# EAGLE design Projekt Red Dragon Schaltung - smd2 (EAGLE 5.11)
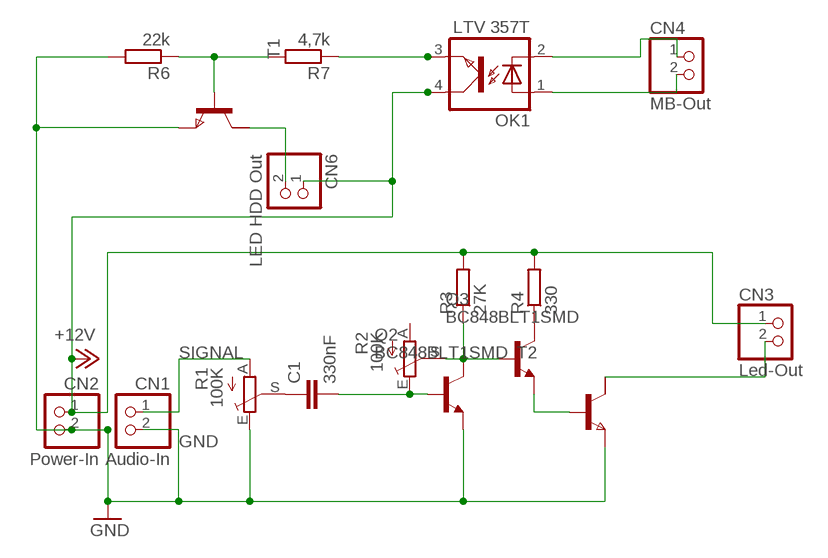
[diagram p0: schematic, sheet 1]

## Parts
C1  330nF  C-EU050-024X044  [C050-024X044]
CN1  Audio-In  PINHD-1X2  [1X02]
CN2  Power-In  PINHD-1X2  [1X02]
CN3  Led-Out  PINHD-1X2  [1X02]
CN4  MB-Out  PINHD-1X2  [1X02]
CN6  LED HDD Out  PINHD-1X2  [1X02]
OK1  LTV 357T  LTV816S  [SMD4]
Q2  BC848BLT1SMD  [SOT23]
Q3  BC848BLT1SMD  [SOT23]
R1  100K  TRIM_EU-S64W  [S64W]
R2  100K  TRIM_EU-S64W  [S64W]
R3  27K  R-EU_R1206  [R1206]
R4  330  R-EU_R1206  [R1206]
R6  22k  R-EU_R1206  [R1206]
R7  4,7k  R-EU_R1206  [R1206]
T1  NPNSOT223  [SOT223]
T2  NPNSOT223  [SOT223]

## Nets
+12V: CN2.1 CN3.1 CN6.1 OK1.4(COL) R3.2 R4.2
GND: CN1.2 CN2.2 Q2.2(E) R1.E R6.2 T1.3(E) T2.3(E)
N$1: C1.1 R1.S
N$2: C1.2 Q2.1(B) R2.E
N$3: Q2.3(C) Q3.1(B) R2.S R3.1
N$4: Q3.3(C) R4.1
N$5: Q3.2(E) T2.1(B)
N$6: CN4.1 OK1.2(C)
N$7: R6.1 R7.2 T1.1(B)
N$8: CN4.2 OK1.1(A)
N$9: CN3.2 T2.2(C1)
N$10: OK1.3(EMIT) R7.1
N$13: CN6.2 T1.2(C1)
SIGNAL: CN1.1 R1.A
Unconnected: R2.A T1.4(C2) T2.4(C2)

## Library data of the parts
C1 = rcl:C-EU: CAPACITOR, European symbol
CN1-CN4 CN6 = pinhead:PINHD-1X2: PIN HEADER
OK1 = optocoupler:LTV816: OPTO COUPLER Source: LITEON, LTV816.pdf
Q2 Q3 = transistor-npn:BC848*: NPN Transistor
R1 R2 = pot:TRIM_EU-: POTENTIOMETER
R3 R4 R6 R7 = rcl:R-EU_: RESISTOR, European symbol
T1 T2 = zetex:NPNSOT223: NPN TRANSISTOR; MPN: DJT4031N-13; OC_FARNELL: 1710672; OC_NEWARK: 25R4490

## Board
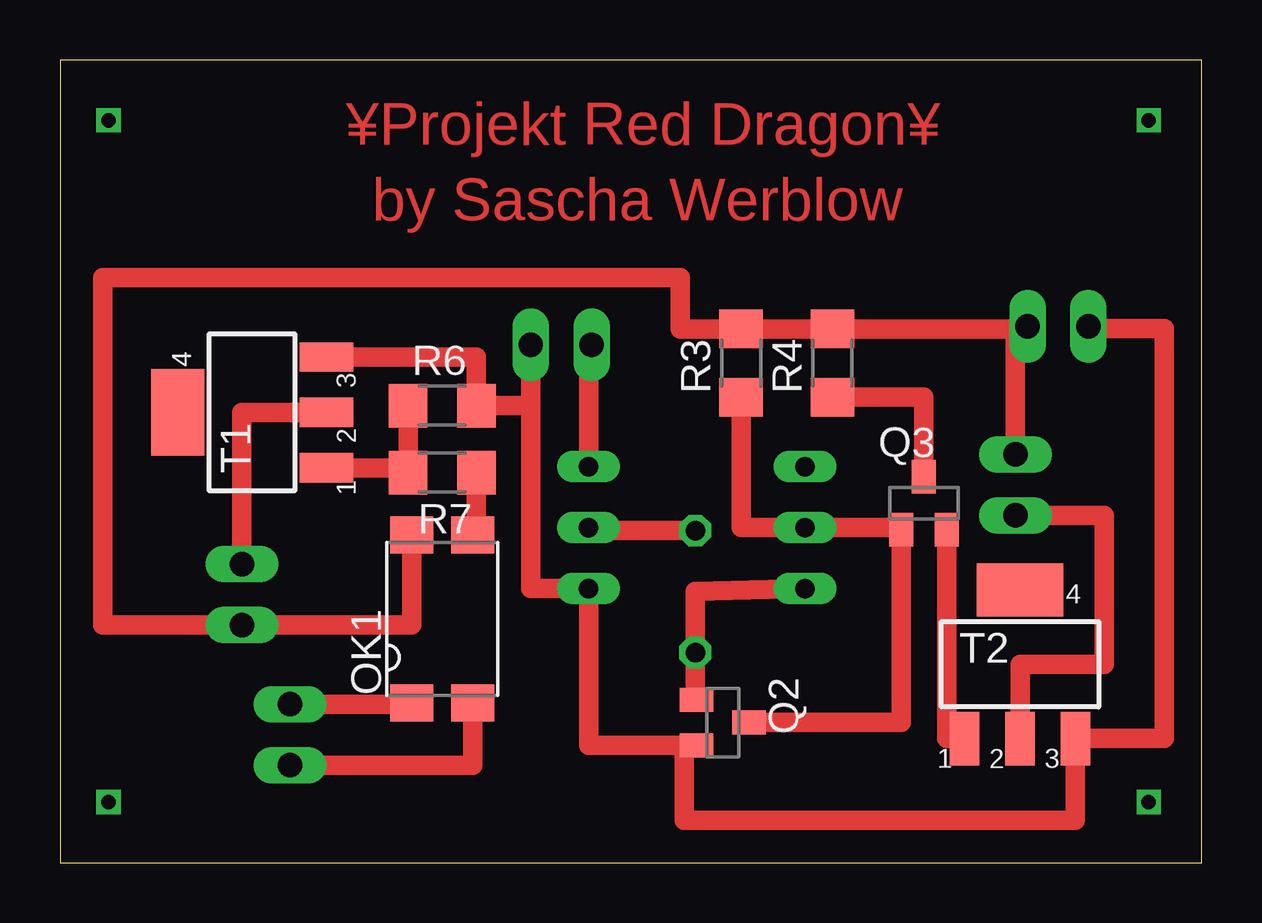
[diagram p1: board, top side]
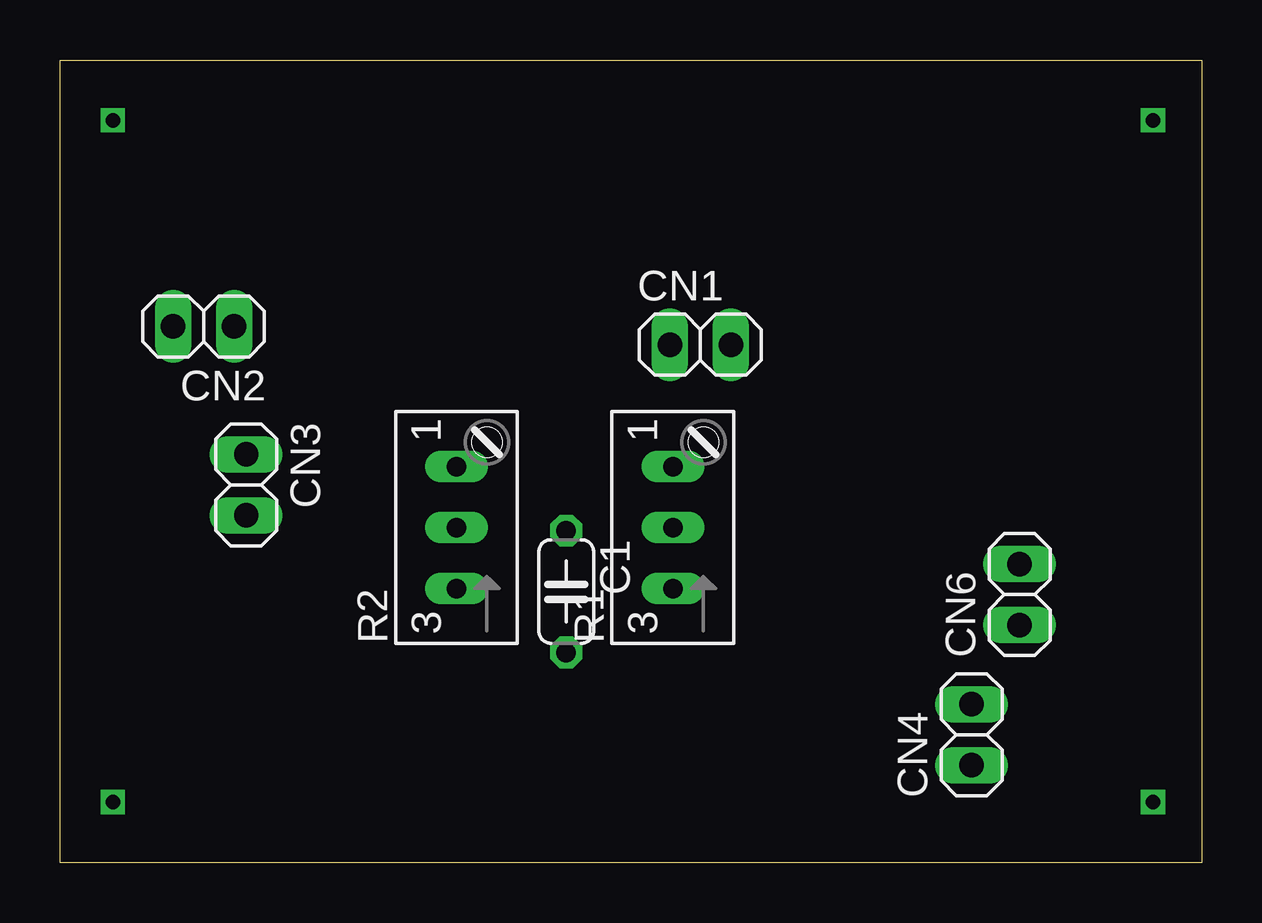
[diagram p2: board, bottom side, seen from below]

Size 47.56 x 33.46 mm. Coordinates in mm from the lower left corner, seen from the top.
Outline: 0,0 47.56,0 47.56,33.46 0,33.46 0,0
Copper layers (1*16): Top 0.035mm / dielectric 1.5mm / Bottom 0.035mm
Design rules "default": minimum track width 10mil, minimum drill 24mil, track to track 8mil, track to pad 8mil, pad to pad 8mil, via to via 8mil, smd to smd 8mil, copper to edge 40mil, drill to drill 8mil, minimum pad ring 10mil, minimum via ring 8mil, stop-mask expansion 4mil, vias tented up to drill 0mil, thermal gap 10mil

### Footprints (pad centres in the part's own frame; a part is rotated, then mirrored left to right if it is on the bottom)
C050-024X044 = drill 0.813 octagon: 1 -2.54,0; 2 2.54,0
1X02 = drill 1.016 long: 1 -1.27,0; 2 1.27,0
SMD4 = smd 1.78 x 1.55: 1 -1.27,-3.5; 2 1.27,-3.5; 3 1.27,3.5; 4 -1.27,3.5
SOT23 = smd 1 x 1.4: 1 -0.95,-1.1; 2 0.95,-1.1; 3 0,1.1
S64W = drill 0.813 long: A 2.54,1.27; E -2.54,1.27; S 0,1.27
R1206 = smd 1.6 x 1.803: 1 -1.422,0; 2 1.422,0
SOT223 = smd 1.219 x 2.235: 1 -2.311,-3.099; 2 0,-3.099; 3 2.311,-3.099 | smd 3.6 x 2.2: 4 0,3.099

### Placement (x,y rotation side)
C1  26.47,11.3 270 bottom
CN1  20.88,21.59 0 bottom
CN2  41.58,22.35 180 bottom
CN3  39.81,15.75 270 bottom
CN4  9.58,5.33 90 bottom
CN6  7.58,11.18 90 bottom
OK1  15.93,10.16 0 top
Q2  27.61,5.84 270 top
Q3  36,14.99 0 top
R1  20.76,13.97 90 bottom
R2  29.77,13.97 90 bottom
R3  28.38,20.83 90 top
R4  32.19,20.83 90 top
R6  15.93,19.05 0 top
R7  15.93,16.26 180 top
T1  8,18.77 90 top
T2  40,8.27 0 top

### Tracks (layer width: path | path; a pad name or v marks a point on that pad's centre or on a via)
+12V
  Top 0.813: OK1.4 14.66,9.91 CN6.1 1.78,9.91 1.78,24.38 25.84,24.38 25.84,22.25 R3.2 R4.2 39.81,22.25 | 39.81,22.25 CN3.1 | CN2.1 39.81,22.35 39.81,22.25
GND
  Top 0.813: 19.61,19.05 CN1.2 | 19.61,19.05 R6.2 17.35,21.08 T1.3 | 19.61,19.05 19.61,11.43 R1.E 22.03,4.89 Q2.2 26,4.89 26,1.77 42.31,1.77 T2.3 46,5.17 46,22.27 42.85,22.27 CN2.2
N$1
  Top 0.813: R1.S 22.03,13.84 C1.1
N$2
  Top 0.813: Q2.1 26.47,6.79 C1.2 26.47,11.3 R2.E
N$3
  Top 0.813: Q2.3 35.05,5.84 Q3.1 35.05,13.97 R2.S 28.38,13.97 R3.1
N$4
  Top 0.813: R4.1 36,19.41 Q3.3
N$5
  Top 0.813: T2.1 36.95,5.17 Q3.2
N$6
  Top 0.813: CN4.1 17.2,4.06 OK1.2
N$7
  Top 0.813: R6.1 R7.2 14.51,16.46 T1.1
N$8
  Top 0.813: OK1.1 14.66,6.6 CN4.2
N$9
  Top 0.813: T2.2 40,8.27 43.5,8.27 43.5,14.48 CN3.2
N$10
  Top 0.813: OK1.3 17.35,13.66 R7.1
N$11  (via drill 0.6)
  other vias: 2.02,30.95
N$12  (via drill 0.6)
  other vias: 45.36,30.95
N$13
  Top 0.813: T1.2 7.58,18.77 CN6.2
N$14  (via drill 0.6)
  other vias: 45.36,2.52
N$15  (via drill 0.6)
  other vias: 2.02,2.52
SIGNAL
  Top 0.813: R1.A 22.03,21.59 CN1.1

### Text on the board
Top: ¥Projekt Red Dragon¥ | by Sascha Werblow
